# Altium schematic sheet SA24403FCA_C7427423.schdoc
size 127 x 101 mm
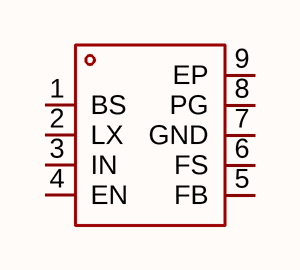
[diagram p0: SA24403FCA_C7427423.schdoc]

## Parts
U?  sa24403fca_c7427423  [ESOP-8_L4.9-W3.9-P1.27-LS6.2-BL-EP]  (value not drawn)

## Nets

Not connected (* = marked no-connect by the designer): U? 1(BS) 2(LX) 3(IN) 4(EN) 5(FB) 6(FS) 7(GND) 8(PG) 9(EP)

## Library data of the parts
U? = sa24403fca_c7427423: 功能类型:降压型;工作电压:4.2V~40V;输出电压:-;输出电流:3.5A;输出类型:可调;; Manufacturer: Silergy(矽力杰); AddInBom: yes; ModelId: 053e850d1a1a4bd9956608cb83b09378; ModelTransform: 192.913,244.094,0,0,0,0,0,0,0; Function: 降压型; Output Current: 3.5A; Frequency - Switching: 300kHz~2.2MHz; Synchronous Rectifier: 是; Number of Outputs: 1; Topology: 降压式; Quiescent Current: 18uA; Switch tube (built-in/external): 内置; Output Type: 可调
